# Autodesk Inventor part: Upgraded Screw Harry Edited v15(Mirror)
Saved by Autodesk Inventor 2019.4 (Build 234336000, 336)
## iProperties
Created: 2020-06
Part Number: Upgraded Screw Harry Edited v15(Mirror)
Material: Generic
Document SubType Name: Modeling
Designer: Administrator
Density: 1 g/cm^3
Appearance: Default
Title: Upgraded Screw Harry Edited v15(Mirror)
Author: Administrator
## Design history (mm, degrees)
